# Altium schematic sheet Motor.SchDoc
size A4; SheetNumber: 3; SheetTotal: 4
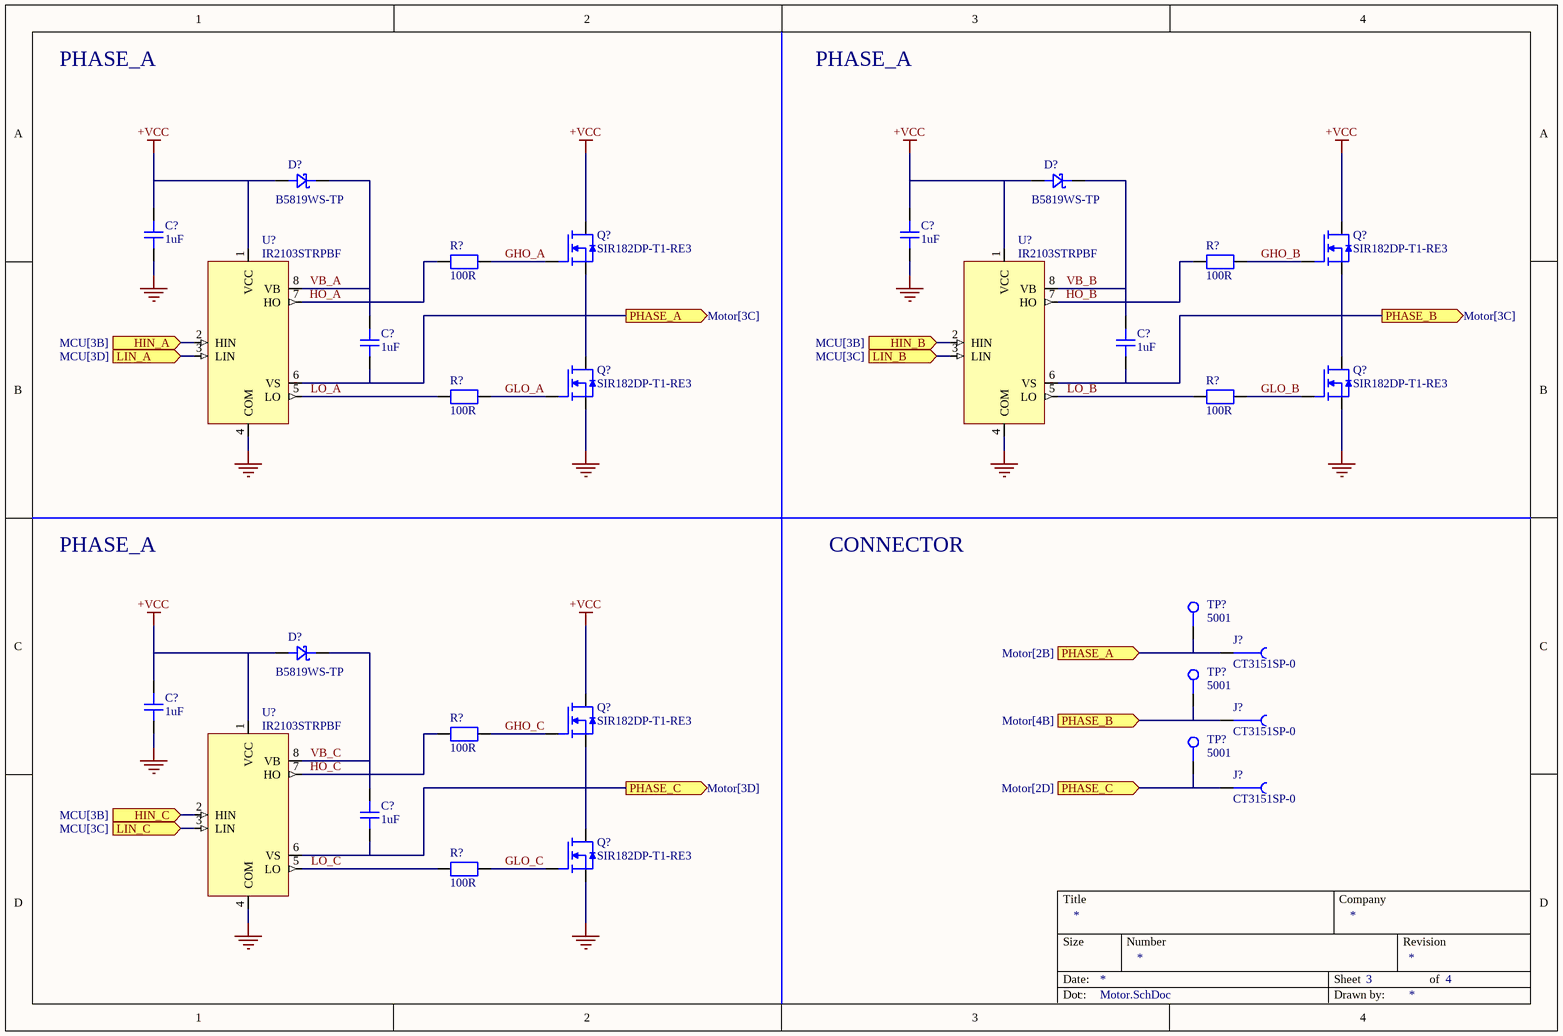
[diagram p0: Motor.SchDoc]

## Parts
(Parts that share a designator on the sheet are numbered #1, #2 ... from top to bottom, then left to right.)
C?#1  value 1uF  [C_Yageo_CC_0603_A]  (hidden comment: CC0603KRX7R7BB105)
C?#2  value 1uF  [C_Yageo_CC_0603_A]  (hidden comment: CC0603KRX7R7BB105)
C?#3  value 1uF  [C_Yageo_CC_0603_A]  (hidden comment: CC0603KRX7R7BB105)
C?#4  value 1uF  [C_Yageo_CC_0603_A]  (hidden comment: CC0603KRX7R7BB105)
C?#5  value 1uF  [C_Yageo_CC_0603_A]  (hidden comment: CC0603KRX7R7BB105)
C?#6  value 1uF  [C_Yageo_CC_0603_A]  (hidden comment: CC0603KRX7R7BB105)
D?#1  B5819WS-TP  [D_Schottky_Micro_SOD-323]
D?#2  B5819WS-TP  [D_Schottky_Micro_SOD-323]
D?#3  B5819WS-TP  [D_Schottky_Micro_SOD-323]
J?#1  CT3151SP-0  [J_CalTest_CT3151SP-0]
J?#2  CT3151SP-0  [J_CalTest_CT3151SP-0]
J?#3  CT3151SP-0  [J_CalTest_CT3151SP-0]
Q?#1  SIR182DP-T1-RE3  [Q_Vishay_PowerPACK-SO-8-Single]
Q?#2  SIR182DP-T1-RE3  [Q_Vishay_PowerPACK-SO-8-Single]
Q?#3  SIR182DP-T1-RE3  [Q_Vishay_PowerPACK-SO-8-Single]
Q?#4  SIR182DP-T1-RE3  [Q_Vishay_PowerPACK-SO-8-Single]
Q?#5  SIR182DP-T1-RE3  [Q_Vishay_PowerPACK-SO-8-Single]
Q?#6  SIR182DP-T1-RE3  [Q_Vishay_PowerPACK-SO-8-Single]
R?#1  value 100R  [R_Yageo_RCL_1206_A]  (hidden comment: RC1206FR-07100RL)
R?#2  value 100R  [R_Yageo_RCL_1206_A]  (hidden comment: RC1206FR-07100RL)
R?#3  value 100R  [R_Yageo_RCL_1206_A]  (hidden comment: RC1206FR-07100RL)
R?#4  value 100R  [R_Yageo_RCL_1206_A]  (hidden comment: RC1206FR-07100RL)
R?#5  value 100R  [R_Yageo_RCL_1206_A]  (hidden comment: RC1206FR-07100RL)
R?#6  value 100R  [R_Yageo_RCL_1206_A]  (hidden comment: RC1206FR-07100RL)
TP?#1  5001  [TP_Keystone_TH]
TP?#2  5001  [TP_Keystone_TH]
TP?#3  5001  [TP_Keystone_TH]
U?#1  IR2103STRPBF  [U_Infineon_8-SOIC_3.9mm]
U?#2  IR2103STRPBF  [U_Infineon_8-SOIC_3.9mm]
U?#3  IR2103STRPBF  [U_Infineon_8-SOIC_3.9mm]

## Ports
HIN_A (in, see MCU[3B]), HIN_B (in, see MCU[3B]), HIN_C (in, see MCU[3B]), LIN_A (in, see MCU[3D]), LIN_B (in, see MCU[3C]), LIN_C (in, see MCU[3C]), PHASE_A (in, see Motor[2B]), PHASE_A (out, see Motor[3C]), PHASE_B (in, see Motor[4B]), PHASE_B (out, see Motor[3C]), PHASE_C (in, see Motor[2D]), PHASE_C (out, see Motor[3D])

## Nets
+VCC: C?#1.2 C?#2.2 C?#5.2 D?#1.2 D?#2.2 D?#3.2 Q?#1.1(D) Q?#2.1(D) Q?#5.1(D) U?#1.1(VCC) U?#2.1(VCC) U?#3.1(VCC)
GND: C?#1.1 C?#2.1 C?#5.1 Q?#3.3(S) Q?#4.3(S) Q?#6.3(S) U?#1.4(COM) U?#2.4(COM) U?#3.4(COM)
GHO_A: Q?#1.2(G) R?#1.2
GHO_B: Q?#2.2(G) R?#2.2
GHO_C: Q?#5.2(G) R?#5.2
GLO_A: Q?#3.2(G) R?#3.2
GLO_B: Q?#4.2(G) R?#4.2
GLO_C: Q?#6.2(G) R?#6.2
HIN_A: U?#1.2(HIN) ; port HIN_A
HIN_B: U?#2.2(HIN) ; port HIN_B
HIN_C: U?#3.2(HIN) ; port HIN_C
HO_A: R?#1.1 U?#1.7(HO)
HO_B: R?#2.1 U?#2.7(HO)
HO_C: R?#5.1 U?#3.7(HO)
LIN_A: U?#1.3(LIN) ; port LIN_A
LIN_B: U?#2.3(LIN) ; port LIN_B
LIN_C: U?#3.3(LIN) ; port LIN_C
LO_A: R?#3.1 U?#1.5(LO)
LO_B: R?#4.1 U?#2.5(LO)
LO_C: R?#6.1 U?#3.5(LO)
PHASE_A: C?#3.1 J?#1.1 Q?#1.3(S) Q?#3.1(D) TP?#1.1 U?#1.6(VS) ; port PHASE_A
PHASE_B: C?#4.1 J?#2.1 Q?#2.3(S) Q?#4.1(D) TP?#2.1 U?#2.6(VS) ; port PHASE_B
PHASE_C: C?#6.1 J?#3.1 Q?#5.3(S) Q?#6.1(D) TP?#3.1 U?#3.6(VS) ; port PHASE_C
VB_A: C?#3.2 D?#1.1 U?#1.8(VB)
VB_B: C?#4.2 D?#2.1 U?#2.8(VB)
VB_C: C?#6.2 D?#3.1 U?#3.8(VB)

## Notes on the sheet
- PHASE_A
- CONNECTOR

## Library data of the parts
C?#1-C?#6 = CMP-001-00019-1: Multilayer Ceramic Capacitor, 1 uF, 16 V, ± 10%, X7R, 0603 [1608 Metric]; Voltage: 16V; Dissipation Factor: 5%
D?#1-D?#3 = CMP-004-00004-1: Rectifier Diode, Schottky, 1 Phase, 1 Element, 1A, 40V V(RRM), Silicon; Peak Non-Repetitive Surge Current: 10A; Value: 48pF; Max Reverse Leakage Current: 1mA; Forward Voltage: 900mV; Max Reverse Current: 7uA
J?#1-J?#3 = CMP-002-00000-11: Conn 4mm Safety Banana Jack F 1 POS Solder RA Thru-Hole 1 Port Bag; pin to pad: 1>1+2+3+4; Gender: Female; Insulation: Mating End Insulated; Body Material: Nylon,Polyamide,PA66
Q?#1-Q?#6 = CMP-013-00000-2: TrenchFET Gen IV Power MOSFET N-Channel Single 60V VDS ±20V VGS 60A ID 8-Pin PowerPAK SOIC T/R; pin to pad: 1>5 2>4 3>1+2+3; Rds On Max: 2.8mR; Max Power Dissipation: 69.4W; Input Capacitance: 3.25nF
R?#1-R?#6 = CMP-009-00004-8: SMD Chip Resistor, 100 Ohm, ± 1%, 250 mW, 1206 [3216 Metric], Thick Film, General Purpose; Max Power Dissipation: 250mW; Voltage Rating (AC): 200V; Temperature Coefficient: 100ppm/°C
TP?#1-TP?#3 = CMP-000000-1: TEST POINT, PCB, THROUGH HOLE; Product R; Range: -; Connector Colour: Black; Mounting: Through Hole; Body Material: Bronze; Insulation: Insulated; Plating: Silver; Number of Ports: 1; Inside Diameter: 1.27mm; Hole Diameter: 1.6mm; Outside Diameter: 2.54mm
U?#1-U?#3 = CMP-024-00000-2: 600 V half-bridge gate driver IC with shoot through protection, SOIC 8N, RoHS; Number of Outputs: 2; Max Supply Voltage: 20V; Propagation Delay: 680ns; Fall Time: 60ns; Channel Type: Independent; Output Current: 360mA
